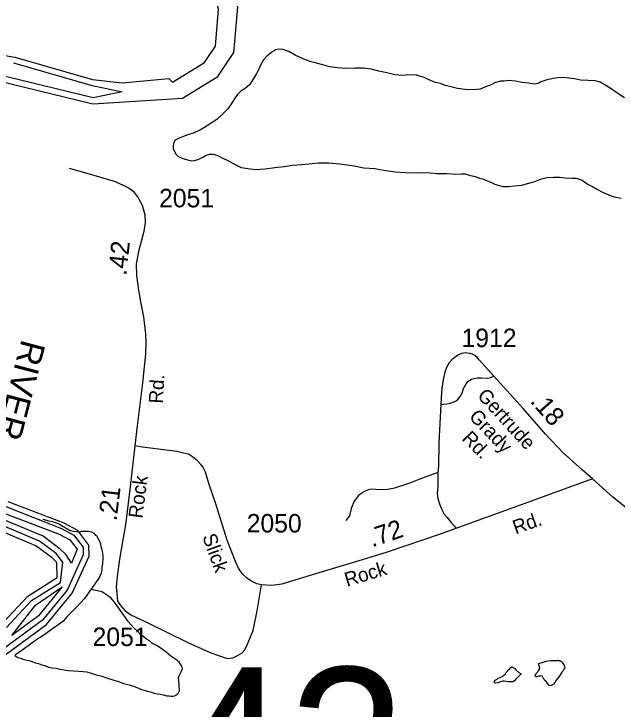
# Model space of a CAD drawing. Extents: x 2206922 to 2357709, y 510027 to 673830.
# Drawn here: x 2317208 to 2321287, y 554312 to 559014 of the extents above; entities that cross this region are included whole.
import ezdxf

# ---------------------------------------------------------------- set-up
doc = ezdxf.new("R2010")
doc.units = 0
for name, color, linetype in [('Exist Hydrographic Buffer Line', 7, 'Continuous'), ('Exist Hydrographic Misc Water Feature', 7, 'Continuous'), ('Exist Hydrographic River Shore', 7, 'Continuous'), ('Exist Hydrographic River Shore Label', 7, 'Continuous'), ('Exist Road Non-System Type 51', 7, 'Continuous'), ('Exist Road Secondary Mileage Hundredths English Label', 7, 'Continuous'), ('Exist Road Secondary Structure Standard Bridge Number Label', 7, 'Continuous'), ('Exist Road Secondary Type 51 Attributed', 7, 'Continuous'), ('Exist Road Secondary Type 51 Label', 7, 'Continuous'), ('Exist Road Secondary Type 51 Number Label', 7, 'Continuous')]:
    doc.layers.add(name, color=color, linetype=linetype)

msp = doc.modelspace()

# ---------------------------------------------------------------- linework, layer by layer
at = {"layer": 'Exist Hydrographic Buffer Line'}
for points in [[(2317204.4, 558682.8), (2317729.1, 558530.8), (2317940.7, 558486.6), (2317743.9, 558445.8), (2317000, 558627)], [(2317142.1, 555685.8), (2317530.6, 555532.2), (2317612.9, 555488.6), (2317675.6, 555407.3), (2317676.4, 555354.2), (2317568.2, 555116.4), (2317401.7, 554913.8), (2317136.7, 554718.4)], [(2317597.9, 555298.4), (2317560.6, 555355.6), (2317521.6, 555393.6), (2317405.1, 555480.9), (2317140.6, 555592.9), (2317103.3, 555650.4), (2317514.2, 555495.7), (2317586.6, 555457.3), (2317635.6, 555393.5), (2317597.9, 555298.4)], [(2317158.3, 554864.8), (2317328.2, 555045.4), (2317522.8, 555168.8), (2317539.5, 555305), (2317493.9, 555364.6), (2317381.2, 555448.7), (2317118.9, 555558.6)], [(2317193.7, 554810.2), (2317353.9, 555014.3), (2317533.9, 555137.8), (2317374, 554943.1), (2317193.7, 554810.2)]]:
    msp.add_lwpolyline(points, dxfattribs=at)
at = {"layer": 'Exist Hydrographic Misc Water Feature'}
for points in [[(2319254.9, 558681), (2319219.2, 558688.8), (2319179, 558702.2), (2319143, 558717.8), (2319110.8, 558733.6), (2319066.5, 558758.9), (2319026.3, 558772.6), (2318998, 558774.4), (2318976.5, 558770), (2318950.6, 558752), (2318920.9, 558729.7), (2318896.9, 558703.3), (2318873.7, 558663), (2318863.7, 558638.9), (2318848.1, 558610.9), (2318820.6, 558566.3), (2318800.9, 558534.4), (2318771.4, 558510.1), (2318743.5, 558491.5), (2318719.5, 558469.6), (2318698, 558437.2), (2318678.5, 558406.9), (2318655.1, 558370.7), (2318617.2, 558332.5), (2318579.5, 558300.1), (2318542, 558275.8), (2318507.9, 558253.3), (2318470.4, 558228.9), (2318426.5, 558208.4), (2318390.4, 558198), (2318358.6, 558185.8), (2318336.9, 558177.2), (2318313.1, 558167), (2318299.4, 558159), (2318289.5, 558143.1), (2318285.8, 558120.9), (2318285.8, 558103), (2318292, 558087.1), (2318304.3, 558063.3), (2318316.4, 558051.4), (2318334.6, 558041.4), (2318350.2, 558035.8), (2318374.4, 558028.1), (2318390.8, 558024), (2318408.5, 558020.5), (2318430.4, 558022.5), (2318450.7, 558028.7), (2318472.4, 558037.2), (2318490.3, 558047.1), (2318508.1, 558059.4), (2318530.3, 558065.4), (2318555.9, 558064), (2318580.1, 558058.3), (2318597.9, 558048.3), (2318626.4, 558034.7), (2318654.7, 558021.2), (2318670.7, 558013.1), (2318690.6, 558001.6), (2318716.7, 557987.9), (2318745, 557975.9), (2318788.8, 557968.6), (2318839.3, 557960.9), (2318906.9, 557965.8), (2318973, 557974.5), (2319034.7, 557981), (2319092.7, 557991.7), (2319152.2, 557994.5), (2319204.3, 557998.9), (2319268.5, 558005.5), (2319336.5, 558006.1), (2319412.2, 557999.2), (2319508.2, 557986), (2319574.8, 557972.7), (2319648.4, 557967.7), (2319722.8, 557954.5), (2319786.6, 557945.3), (2319856.7, 557940), (2319934.9, 557938.8), (2320002.7, 557941.5), (2320068.8, 557934.1), (2320136.4, 557934.8), (2320196.7, 557929.4), (2320234.5, 557931.8), (2320260.5, 557932.4), (2320294.7, 557920.7), (2320330.4, 557912.9), (2320356.9, 557903.3), (2320382.9, 557895.7), (2320409.2, 557885.7), (2320433.1, 557876), (2320459.2, 557862.3), (2320481.3, 557854.5), (2320513.7, 557846.9), (2320549.6, 557845.5), (2320593.7, 557849.8), (2320643.1, 557856.5), (2320681.5, 557866.6), (2320723.1, 557879), (2320768.8, 557895.6), (2320814.5, 557908.2)], [(2321336.2, 558445.7), (2321284.5, 558479), (2321246.2, 558506.7), (2321209.7, 558530), (2321173.4, 558551.7), (2321137.5, 558561.5), (2321091.4, 558562.8), (2321039.3, 558566.2), (2320999.3, 558573.8), (2320941.5, 558581.3), (2320911.1, 558583), (2320885.7, 558580.4), (2320855.6, 558576.4), (2320837.5, 558572.2), (2320817.6, 558569.9), (2320793.6, 558561.8), (2320771.5, 558553.4), (2320752, 558543.3), (2320726.2, 558538.7), (2320689.7, 558544.6), (2320641.7, 558549.8), (2320599.6, 558557.7), (2320556, 558563.1), (2320523.8, 558558.6), (2320497.7, 558558.4), (2320464.1, 558550.1), (2320430.5, 558531.7), (2320396, 558519.4), (2320360.6, 558504.9), (2320316.5, 558500.6), (2320260.5, 558502.1), (2320206.6, 558509.4), (2320162.5, 558520.9), (2320124.1, 558530.3), (2320092.1, 558542), (2320058.1, 558549.6), (2320025.9, 558563.4), (2319981.6, 558583), (2319933.6, 558598.4), (2319883.6, 558601.8), (2319837.9, 558597.3), (2319784, 558602.6), (2319729.6, 558614.1), (2319675.5, 558625.4), (2319623.2, 558639), (2319569.3, 558646.7), (2319513.5, 558647.8), (2319451.4, 558645.4), (2319395.4, 558648.5), (2319343.5, 558655.9), (2319297.2, 558669.4), (2319254.9, 558681)], [(2320814.5, 557908.2), (2320856.8, 557908.7), (2320900.7, 557909), (2320934.9, 557905.5), (2320980.6, 557901.9), (2321010.8, 557902.2), (2321050.8, 557888.9), (2321085, 557865.1), (2321121.1, 557847.5), (2321153.3, 557826), (2321187.7, 557808.3), (2321232, 557790.6), (2321267.5, 557777.2), (2321314, 557767.8)], [(2317403.3, 555596.8), (2317443.5, 555585.1), (2317469.3, 555579.5), (2317493.5, 555571.9), (2317513.4, 555564), (2317529.6, 555554.3), (2317541.5, 555546.4), (2317562.2, 555534.7), (2317587.8, 555520.7), (2317612, 555515.1), (2317632.1, 555513.3), (2317651.8, 555511.5), (2317666, 555515.5), (2317680.1, 555515.8), (2317695.9, 555515.9), (2317715.8, 555516.1), (2317732, 555510.4), (2317748.2, 555500.7), (2317756.2, 555492.6), (2317766.4, 555485), (2317772.4, 555472.7), (2317784.5, 555451), (2317792.7, 555429.1), (2317797, 555411), (2317803.1, 555391.5), (2317809.5, 555351.5), (2317809.9, 555335.3), (2317806.2, 555295.3), (2317802.1, 555271.1), (2317802.7, 555251.2), (2317797.2, 555233.4), (2317789.2, 555209), (2317777.3, 555190.9), (2317728.3, 555120.5)], [(2317728.3, 555120.5), (2317685, 555060), (2317659.2, 555029.9), (2317633.6, 555003.8), (2317599.7, 554969.5), (2317568, 554937), (2317540.5, 554906.7), (2317505, 554880.3), (2317463, 554849.8), (2317417.7, 554817.3), (2317382.2, 554793), (2317348.1, 554770.5), (2317320.7, 554750.4), (2317288.5, 554728), (2317253, 554701.7), (2317221.2, 554681.4), (2317213.4, 554675.3)], [(2317213.4, 554675.3), (2317235.4, 554661.4), (2317255.7, 554655.9), (2317269.4, 554649.8), (2317287.2, 554644.3), (2317309.6, 554640.5), (2317331.7, 554632.7), (2317351.6, 554624.9), (2317373.6, 554619.1), (2317389.8, 554613.4), (2317417.7, 554605.6), (2317442.1, 554595.9), (2317465.6, 554590.2), (2317493.9, 554588.4), (2317517.9, 554582.8), (2317548.1, 554577), (2317576.4, 554573.2), (2317612.2, 554569.8), (2317648.1, 554568.1), (2317676.4, 554566.2), (2317702.1, 554562.8), (2317730.1, 554554.9), (2317764.4, 554543.3), (2317802.3, 554533.5), (2317840.3, 554522.1), (2317876.6, 554510.6), (2317914.7, 554498.8), (2317951, 554485.2), (2317986.9, 554475.7), (2318021.1, 554464.1), (2318047.2, 554454.5), (2318070.9, 554444.8), (2318089.2, 554438.8), (2318111.5, 554433), (2318137.4, 554425.5), (2318157.3, 554419.7), (2318181.5, 554414), (2318197.3, 554412), (2318217.6, 554408.2), (2318241.5, 554402.5), (2318249.8, 554402.5), (2318255.7, 554400.8), (2318271.5, 554398.8), (2318283.6, 554399.1), (2318295.7, 554400.9), (2318301.6, 554405.3), (2318307.4, 554407.2), (2318317.6, 554417.4), (2318321.7, 554421.3), (2318327.5, 554435.4), (2318327.3, 554445.1), (2318325.2, 554465.3), (2318324.6, 554477.2), (2318322.5, 554493.3), (2318322.3, 554507.1), (2318322.1, 554523.4), (2318326, 554537.4), (2318332, 554549.5), (2318339.8, 554563.3), (2318347.8, 554583.6), (2318345.7, 554593.7), (2318339.4, 554609.6), (2318325.2, 554629.2), (2318302.7, 554647.2), (2318268.8, 554670.5), (2318236.6, 554696.4), (2318212.2, 554715.9), (2318196.4, 554725.6), (2318171.8, 554741.5), (2318146, 554755.1), (2318125.7, 554773.2), (2318105.4, 554784.7), (2318083.2, 554802.7), (2318062.9, 554818.3), (2318042.9, 554837.9), (2318020.7, 554859.9), (2318000.4, 554881.6), (2317980.7, 554903.2), (2317960.2, 554933.1), (2317944.2, 554955), (2317921.5, 554986.8), (2317905.5, 555010.7), (2317885.2, 555036.5), (2317864.7, 555062.2), (2317840.5, 555079.7), (2317820.2, 555093.7), (2317802.1, 555105.3), (2317774.2, 555111.1), (2317728.3, 555120.5)], [(2320900.7, 554538.8), (2320883, 554518.8), (2320875, 554506.6), (2320865, 554492.7), (2320855.3, 554478.3), (2320841.4, 554470.3), (2320829.3, 554470.1), (2320821.7, 554480.2), (2320815.4, 554488), (2320805.5, 554500), (2320796.9, 554507.8), (2320791, 554515.6), (2320786.9, 554523.9), (2320785, 554527.8), (2320783.2, 554531.8), (2320780.7, 554535.8), (2320774.8, 554535.5), (2320770.7, 554535.7), (2320764.5, 554535.4), (2320752.8, 554533.5), (2320744.8, 554529.4), (2320739.3, 554531.1), (2320733.1, 554535.3), (2320732.9, 554539), (2320734.8, 554543.1), (2320736.8, 554549.3), (2320740.7, 554553.2), (2320744.8, 554557.4), (2320748.5, 554561.3), (2320750.6, 554565.5), (2320754.5, 554571.4), (2320758.4, 554577.3), (2320764.3, 554587.4), (2320762.3, 554597.4), (2320760, 554605.4), (2320757.9, 554613.4), (2320757.7, 554619.5), (2320779.5, 554627.6), (2320807.8, 554635.9), (2320835.7, 554640.3), (2320843.7, 554640.3), (2320848, 554640.5), (2320855.6, 554640.5), (2320863.8, 554640.5), (2320883.6, 554640.7), (2320890, 554642.6), (2320897.8, 554639), (2320906, 554639), (2320909.5, 554634.8), (2320914, 554630.9), (2320915.4, 554627), (2320921.8, 554617.1), (2320930.2, 554605.4), (2320932, 554599.4), (2320932.4, 554591.2), (2320926.5, 554581.2), (2320920.8, 554569.1), (2320914.2, 554561.1), (2320900.7, 554538.8)], [(2320638.6, 554550.3), (2320626.7, 554539.9), (2320619.1, 554531.7), (2320610.9, 554523.6), (2320605.2, 554517.6), (2320593.1, 554503.6), (2320581, 554497.3), (2320567.5, 554495.3), (2320549.2, 554497.2), (2320537.5, 554499), (2320525, 554500.9), (2320513.1, 554501), (2320505.5, 554498.5), (2320491.4, 554494.6), (2320483.6, 554488.5), (2320467.4, 554486.4), (2320461.2, 554490.2), (2320455.5, 554494.3), (2320457.3, 554500.1), (2320461.4, 554506.4), (2320475, 554514.5), (2320483.4, 554520.6), (2320497.1, 554526.6), (2320504.9, 554530.7), (2320519.1, 554538.7), (2320528.9, 554549), (2320534.9, 554557), (2320541, 554562.9), (2320548.2, 554571.2), (2320554.7, 554579.1), (2320562.5, 554585.2), (2320566.4, 554591.1), (2320570.3, 554593.5), (2320576.5, 554597.3), (2320582.2, 554593.7), (2320592.1, 554589.7), (2320602.5, 554577.6), (2320622.8, 554560), (2320638.6, 554550.3)]]:
    msp.add_lwpolyline(points, dxfattribs=at)
at = {"layer": 'Exist Hydrographic River Shore'}
for points in [[(2318348.9, 558442.8), (2318587.7, 558590.8), (2318695.3, 558752.5), (2318722.1, 559058.5), (2318706.9, 559113.4)], [(2318281.3, 558551.7), (2318496.4, 558685.1), (2318570.5, 558796.3), (2318592.4, 559046.6), (2318583.4, 559079.1)], [(2316737.3, 558801.2), (2317213.4, 558721.9), (2317740.4, 558569.3), (2317940.3, 558547.7), (2318256.5, 558576.9), (2318281.3, 558551.7)], [(2316990.3, 558588.2), (2317741.4, 558405.2), (2318348.9, 558442.8)], [(2317156.4, 554683.3), (2317429.3, 554884.6), (2317602.4, 555095.1), (2317716.4, 555345.7), (2317715.4, 555421.2), (2317639.5, 555519.9), (2317547.4, 555568.6), (2317170.4, 555714.3)], [(2317137.3, 554899.1), (2317302.4, 555076.3), (2317501.5, 555202.6), (2317499.5, 555304.2), (2317466.5, 555335.7), (2317357.4, 555416.6), (2317097.4, 555524.2)]]:
    msp.add_lwpolyline(points, dxfattribs=at)
at = {"layer": 'Exist Road Non-System Type 51'}
for points in [[(2320454.2, 556563.2), (2320394.7, 556629.1), (2320357.4, 556672.4), (2320340.4, 556689.5), (2320324.5, 556704.2), (2320307.5, 556712.2), (2320290.5, 556717.9), (2320273.5, 556720.1), (2320264.4, 556721.3), (2320248.5, 556720.1), (2320234.9, 556716.7), (2320219, 556709.9), (2320202, 556699.7), (2320185, 556688.3), (2320169.1, 556674.7), (2320148.7, 556652), (2320132.8, 556621.4), (2320122.6, 556590.7), (2320110.1, 556541.9), (2320102.1, 556482.9), (2320096.5, 556418.1), (2320095.3, 556371.6)], [(2320095.3, 556371.6), (2320136.2, 556376.1), (2320158.9, 556380.7), (2320179.3, 556387.5), (2320194.1, 556395.4), (2320207.7, 556404.5), (2320216.7, 556414.7), (2320224.7, 556426.1), (2320236, 556443.1), (2320242.8, 556464.7), (2320247.4, 556480.6), (2320256.5, 556496.5), (2320265.5, 556512.4), (2320278, 556527.1), (2320290.5, 556537.3), (2320301.8, 556543), (2320318.9, 556548.7), (2320342.7, 556553.2), (2320372.2, 556553.2), (2320413, 556551), (2320430.1, 556554.4), (2320454.2, 556563.2)], [(2320095.3, 556371.6), (2320080.7, 556113.1), (2320078.5, 555953.7), (2320074.1, 555912.2)], [(2320074.1, 555912.2), (2319945.4, 555864.2), (2319877.7, 555838), (2319781.7, 555805.3), (2319735.9, 555796.5), (2319681.3, 555794.3), (2319629, 555798.7), (2319602.8, 555794.3), (2319578.8, 555783.4), (2319537.3, 555757.2), (2319508.9, 555717.9), (2319489.3, 555667.7), (2319478.4, 555619.7), (2319453.3, 555586.9)], [(2320074.1, 555912.2), (2320074.1, 555818.4), (2320069.8, 555770.3), (2320074.1, 555735.4), (2320085, 555700.5), (2320100.3, 555665.5), (2320117.8, 555630.6), (2320137.4, 555606.6), (2320165.8, 555573.8), (2320185.4, 555552), (2320198.5, 555532.3)], [(2317928, 555013.3), (2317957.2, 554979.2), (2317998.6, 554948.8), (2318109.3, 554897.6), (2318383.9, 554761.9), (2318540.5, 554691.6), (2318649.6, 554652.9), (2318687.4, 554659), (2318720.2, 554673.6), (2318750.6, 554691.8), (2318770.1, 554712.5), (2318784.7, 554745.4), (2318824.9, 554844.1), (2318854.1, 554975.6), (2318883.3, 555152.1)]]:
    msp.add_lwpolyline(points, dxfattribs=at)
at = {"layer": 'Exist Road Secondary Type 51 Attributed'}
for points in [[(2317582.4, 557969.7), (2317684.6, 557940.5), (2317788, 557912.5), (2317892.7, 557880.8), (2317956, 557851.6), (2317987.6, 557834.6), (2318015.6, 557813.9), (2318030.2, 557795.6), (2318048.4, 557770), (2318076.4, 557720.1), (2318093.5, 557655.6), (2318095.9, 557603.2), (2318086.2, 557542.3), (2318049.7, 557407.2), (2318035.1, 557321.9), (2318036.3, 557245.2), (2318050.9, 557145.4), (2318065.1, 557067.1), (2318084.3, 556965.5), (2318098.3, 556849.5), (2318099.6, 556787.4), (2318098.3, 556713.1), (2318075.2, 556497.6), (2318042.4, 556228.5), (2318026.5, 556092.1)], [(2321120, 555868.7), (2321049.5, 555930.2), (2320922.9, 556045.9), (2320803.6, 556171.3), (2320651.5, 556344.2), (2320454.2, 556563.2)], [(2318026.5, 556092.1), (2317993.7, 555816.9), (2317964.5, 555574.6), (2317921.9, 555326.2), (2317906.1, 555209.3), (2317900, 555138.7), (2317904.8, 555096.1), (2317909.7, 555042.5), (2317928, 555013.3)], [(2321120, 555868.7), (2320736.7, 555729.9), (2320090.5, 555494.3), (2319724.2, 555371.3), (2319541.5, 555315.6), (2319270.9, 555233.1), (2319020.8, 555156.4), (2318951.4, 555147.7), (2318883.3, 555152.1), (2318851.6, 555159.4), (2318813.9, 555177.7), (2318783.5, 555197.2), (2318751.9, 555230), (2318727.5, 555264.1), (2318705.6, 555310.4), (2318650.8, 555455.3), (2318574.2, 555700), (2318529.1, 555831.6), (2318503.4, 555914.6), (2318485.3, 555949.7), (2318473.2, 555966.7), (2318450, 555991.1), (2318416, 556019.1), (2318389.2, 556034.9), (2318346.6, 556045.9), (2318308.9, 556053.2), (2318077.6, 556083.8), (2318026.5, 556092.1)], [(2325121.4, 556002), (2324458.8, 555994.7), (2324285.5, 555993.8), (2323779.7, 555991.1), (2323436.5, 555967.3), (2323352.5, 555958.2), (2323243, 555938.1), (2323053.2, 555877.8), (2322836.5, 555798.3), (2322669.8, 555737.2), (2322091.2, 555527.1), (2322002.9, 555506.3), (2321959.7, 555496.1), (2321868.5, 555483.3), (2321786.3, 555481.5), (2321729.7, 555487), (2321658.5, 555505.2), (2321574.6, 555534.4), (2321492.4, 555569.2), (2321423.1, 555613), (2321333.6, 555684.2), (2321257, 555746.3), (2321120, 555868.7)]]:
    msp.add_lwpolyline(points, dxfattribs=at)

# ---------------------------------------------------------------- texts
at = {"layer": 'Exist Hydrographic River Shore Label'}
msp.add_text('RIVER', height=167.32, rotation=255.2923, dxfattribs=at).set_placement((2317261.1, 556818.5))
at = {"layer": 'Exist Road Secondary Mileage Hundredths English Label'}
for s, rotation, p in [('.42', 83.8764, (2317968.2, 557240.3)), ('.18', 311.341, (2320694.2, 556390.3)), ('.21', 83.1266, (2317902.2, 555580.4)), ('.72', 18.5591, (2319630.2, 555405.7))]:
    msp.add_text(s, height=125, rotation=rotation, dxfattribs=at).set_placement(p)
at = {"layer": 'Exist Road Secondary Structure Standard Bridge Number Label'}
msp.add_text('42', height=1066.27, dxfattribs=at).set_placement((2318269.6, 553527))
at = {"layer": 'Exist Road Secondary Type 51 Label'}
for s, rotation, p in [('Rd.', 86.3859, (2318214.3, 556376.2)), ('Gertrude', 312.4424, (2320335.7, 556427.7)), ('Grady', 313.7957, (2320280, 556284.7)), ('Rd.', 314.7974, (2320232.3, 556136.5)), ('Rock', 82.5789, (2318076, 555598.1)), ('Rd.', 19.4503, (2320600.8, 555492.7)), ('Slick', 289.7614, (2318480.7, 555479.3)), ('Rock', 16.686, (2319459.9, 555139.3))]:
    msp.add_text(s, height=95, rotation=rotation, dxfattribs=at).set_placement(p)
at = {"layer": 'Exist Road Secondary Type 51 Number Label'}
for s, p in [('2051', (2318189.7, 557705.5)), ('1912', (2320234.8, 556760.1)), ('2050', (2318782.3, 555506.3)), ('2051', (2317740.3, 554738.4))]:
    msp.add_text(s, height=125, dxfattribs=at).set_placement(p)

doc.saveas('drawing.dxf')
